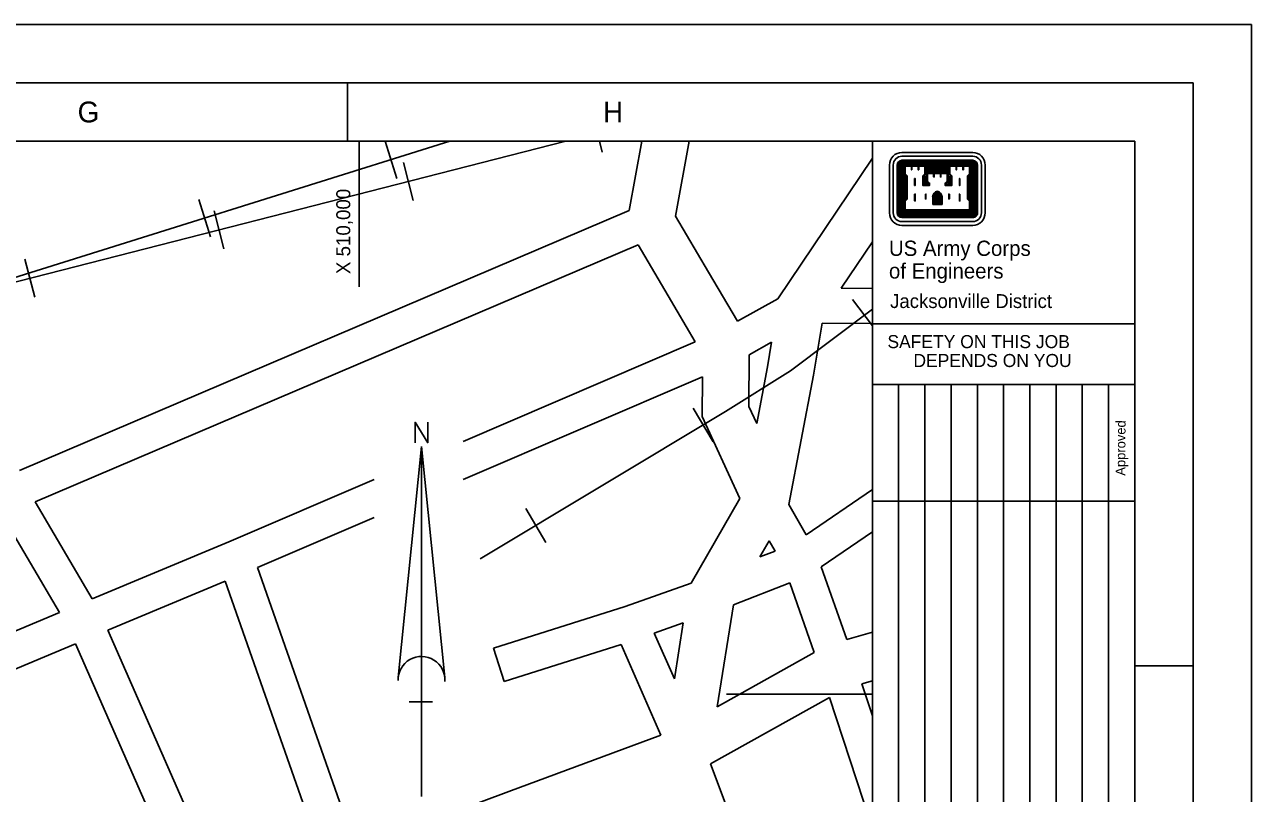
# Model space of a CAD drawing. Extents: x 503330 to 511530, y 1310349 to 1316149.
# Drawn here: x 509426 to 511530, y 1314830 to 1316149 of the extents above; entities that cross this region are included whole.
import ezdxf

# ---------------------------------------------------------------- set-up
doc = ezdxf.new("R2010")
doc.units = 0
for name, color, linetype in [('G-ANNO-SYMB', 7, 'Continuous'), ('G-ANNO-TEXT', 7, 'Continuous'), ('G-ANNO-TTLB', 7, 'Continuous'), ('Level 2', 7, 'Continuous'), ('Level 23', 7, 'Continuous'), ('Level 3', 7, 'Continuous'), ('Level 32', 7, 'Continuous'), ('Level 37', 7, 'Continuous')]:
    doc.layers.add(name, color=color, linetype=linetype)

msp = doc.modelspace()

# ---------------------------------------------------------------- linework, layer by layer
at = {"layer": 'G-ANNO-SYMB'}
for p, q in [((511052.5, 1315928.9), (510930.9, 1315928.9)), ((510930.9, 1315922.5), (511052.5, 1315922.5)), ((511052.5, 1315915.7), (510930.9, 1315915.7)), ((511052.5, 1315913.9), (510930.9, 1315913.9)), ((511052.5, 1315912.1), (510930.9, 1315912.1)), ((510909.5, 1315907.5), (510909.5, 1315825.5)), ((510915.9, 1315825.5), (510915.9, 1315907.5)), ((510922.9, 1315907.5), (510922.9, 1315825.5)), ((510924.7, 1315907.5), (510924.7, 1315825.5)), ((510926.3, 1315907.5), (510926.3, 1315825.5)), ((510928.1, 1315907.5), (510928.1, 1315825.5)), ((510929.9, 1315907.5), (510929.9, 1315825.5)), ((511052.5, 1315910.5), (510930.9, 1315910.5)), ((511052.5, 1315908.7), (510930.9, 1315908.7)), ((510931.7, 1315907.5), (510931.7, 1315826.1)), ((510933.3, 1315907.5), (510933.3, 1315827.9)), ((510973.1, 1315907.1), (511010.3, 1315907.1)), ((510973.1, 1315905.3), (511010.3, 1315905.3)), ((510973.1, 1315903.7), (511010.3, 1315903.7)), ((510973.1, 1315901.9), (511010.3, 1315901.9)), ((510973.1, 1315900.1), (511010.3, 1315900.1)), ((510973.1, 1315898.5), (511010.3, 1315898.5)), ((510973.1, 1315896.7), (511010.3, 1315896.7)), ((511050.1, 1315907.5), (511050.1, 1315827.9)), ((511051.7, 1315907.5), (511051.7, 1315826.1)), ((511053.5, 1315907.5), (511053.5, 1315825.5)), ((511055.3, 1315907.5), (511055.3, 1315825.5)), ((511056.9, 1315907.5), (511056.9, 1315825.5)), ((511058.7, 1315907.5), (511058.7, 1315825.5)), ((511060.5, 1315907.5), (511060.5, 1315825.5)), ((511067.3, 1315907.5), (511067.3, 1315825.5)), ((511073.9, 1315825.5), (511073.9, 1315907.5)), ((510934.7, 1315890.1), (510934.7, 1315848.1)), ((510936.5, 1315888.3), (510936.5, 1315850.1)), ((511046.9, 1315888.3), (511046.9, 1315850.1)), ((511048.7, 1315889.9), (511048.7, 1315848.3)), ((510983.7, 1315839.7), (510983.7, 1315853.1)), ((510985.3, 1315839.7), (510985.3, 1315853.1)), ((510987.1, 1315839.7), (510987.1, 1315853.1)), ((510988.9, 1315839.7), (510988.9, 1315853.1)), ((510990.5, 1315839.7), (510990.5, 1315853.1)), ((510992.9, 1315839.7), (510992.9, 1315853.1)), ((510994.5, 1315839.7), (510994.5, 1315853.1)), ((510996.3, 1315839.7), (510996.3, 1315853.1)), ((510998.1, 1315839.7), (510998.1, 1315853.1)), ((510999.7, 1315839.7), (510999.7, 1315853.1)), ((511050.1, 1315827.9), (510933.3, 1315827.9)), ((510983.7, 1315839.7), (510999.7, 1315839.7)), ((511052.5, 1315824.3), (510930.9, 1315824.3)), ((511052.5, 1315822.7), (510930.9, 1315822.7)), ((511052.5, 1315820.9), (510930.9, 1315820.9)), ((511052.5, 1315819.1), (510930.9, 1315819.1)), ((511052.5, 1315817.5), (510930.9, 1315817.5)), ((511052.5, 1315810.5), (510930.9, 1315810.5)), ((511051.7, 1315826.1), (510931.7, 1315826.1)), ((510930.9, 1315803.9), (511052.5, 1315803.9))]:
    msp.add_line(p, q, dxfattribs=at)
for points in [[(510934.7, 1315907.5), (510934.7, 1315891.7), (510938.1, 1315888.3), (510938.1, 1315850.1), (510934.7, 1315846.5), (510934.7, 1315829.1), (511048.7, 1315829.1), (511048.7, 1315846.5), (511045.1, 1315850.1), (511045.1, 1315888.3), (511048.7, 1315891.7), (511048.7, 1315907.5), (511033.7, 1315907.5), (511022.1, 1315907.5), (511011.3, 1315907.5), (511011.3, 1315891.7), (511015.1, 1315888.3), (511015.1, 1315874.3), (511006.7, 1315874.3), (511006.7, 1315875.7), (511010.3, 1315879.3), (511010.3, 1315894.9), (510995.3, 1315894.9), (510983.7, 1315894.9), (510973.1, 1315894.9), (510973.1, 1315879.3), (510976.7, 1315875.7), (510976.7, 1315874.3), (510968.3, 1315874.3), (510968.3, 1315888.3), (510971.9, 1315891.7), (510971.9, 1315907.5), (510956.9, 1315907.5), (510945.3, 1315907.5), (510934.7, 1315907.5)], [(510936.3, 1315905.7), (510936.3, 1315892.5), (510939.9, 1315888.9), (510939.9, 1315849.3), (510936.3, 1315845.7), (510936.3, 1315830.9), (511047.1, 1315830.9), (511047.1, 1315845.7), (511043.3, 1315849.3), (511043.3, 1315888.9), (511047.1, 1315892.5), (511047.1, 1315905.7), (511036.3, 1315905.7), (511036.3, 1315899.5), (511035.3, 1315899.5), (511035.3, 1315905.7), (511024.7, 1315905.7), (511024.7, 1315899.5), (511023.9, 1315899.5), (511023.9, 1315905.7), (511013.1, 1315905.7), (511013.1, 1315892.5), (511016.7, 1315888.9), (511016.7, 1315872.7), (511005.1, 1315872.7), (511005.1, 1315876.5), (511008.7, 1315880.1), (511008.7, 1315893.3), (510997.9, 1315893.3), (510997.9, 1315887.1), (510997.1, 1315887.1), (510997.1, 1315893.3), (510986.3, 1315893.3), (510986.3, 1315887.1), (510985.3, 1315887.1), (510985.3, 1315893.3), (510974.7, 1315893.3), (510974.7, 1315880.1), (510978.3, 1315876.5), (510978.3, 1315872.7), (510966.7, 1315872.7), (510966.7, 1315888.9), (510970.3, 1315892.5), (510970.3, 1315905.7), (510959.7, 1315905.7), (510959.7, 1315899.5), (510958.7, 1315899.5), (510958.7, 1315905.7), (510947.9, 1315905.7), (510947.9, 1315899.5), (510947.1, 1315899.5), (510947.1, 1315905.7), (510936.3, 1315905.7)], [(510952.7, 1315884.3), (510952.7, 1315872.7), (510953.9, 1315872.7), (510953.9, 1315884.3), (510952.7, 1315884.3)], [(510971.1, 1315888.5), (510970.1, 1315887.5), (510970.1, 1315876.1), (510973.9, 1315876.1), (510971.3, 1315878.7), (510971.3, 1315888.7)], [(511012.3, 1315888.5), (511013.3, 1315887.5), (511013.3, 1315876.1), (511009.7, 1315876.1), (511012.1, 1315878.7), (511012.1, 1315888.7)], [(511030.5, 1315884.3), (511030.5, 1315872.7), (511029.5, 1315872.7), (511029.5, 1315884.3), (511030.5, 1315884.3)], [(510952.7, 1315857.7), (510952.7, 1315845.9), (510953.9, 1315845.9), (510953.9, 1315857.7), (510952.7, 1315857.7)], [(510971.1, 1315857.7), (510971.1, 1315849.5), (510972.1, 1315849.5), (510972.1, 1315857.7), (510971.1, 1315857.7)], [(511012.3, 1315857.7), (511012.3, 1315849.5), (511011.3, 1315849.5), (511011.3, 1315857.7), (511012.3, 1315857.7)], [(511030.5, 1315857.7), (511030.5, 1315845.9), (511029.5, 1315845.9), (511029.5, 1315857.7), (511030.5, 1315857.7)]]:
    msp.add_lwpolyline(points, dxfattribs=at)
for centre, major_axis, start_param, end_param in [((510931, 1315907.6), (21.4, 0), 1.57078, 3.141576), ((510931, 1315907.6), (15, 0), 1.57078, 3.141576), ((510931, 1315907.6), (8.04, 0), 1.57078, 3.141576), ((510931, 1315907.6), (6.3, 0), 1.57078, 3.141576), ((510931, 1315907.6), (4.56, 0), 1.57078, 3.141576), ((511052.4, 1315907.6), (21.4, 0), 6.283169, 7.853965), ((511052.4, 1315907.6), (15, 0), 6.28317, 7.853966), ((511052.4, 1315907.6), (8.04, 0), 6.283169, 7.853965), ((511052.4, 1315907.6), (6.3, 0), 6.283169, 7.853965), ((511052.4, 1315907.6), (4.56, 0), 6.283169, 7.853965), ((510931, 1315907.6), (2.83, 0), 1.57078, 3.141576), ((510931, 1315907.6), (1.09, 0), 1.57078, 3.141576), ((511052.4, 1315907.6), (2.83, 0), 6.283169, 7.853965), ((511052.4, 1315907.6), (1.09, 0), 6.283169, 7.853965), ((510994.7, 1315852.2), (-11.1, 0), 4.985832, 6.214359), ((510994.7, 1315852.2), (-9.37, 0), 4.947465, 6.21436), ((510994.7, 1315852.2), (-7.63, 0), 4.947465, 6.21436), ((510994.7, 1315852.2), (-5.9, 0), 4.947465, 6.21436), ((510988.7, 1315852.2), (4.16, 0), 0.068794, 1.335689), ((510988.7, 1315852.2), (5.9, 0), 0.068794, 1.335689), ((510988.7, 1315852.2), (7.63, 0), 0.068795, 1.335689), ((510994.7, 1315852.2), (-4.16, 0), 4.947465, 6.214359), ((510988.7, 1315852.2), (9.37, 0), 0.068795, 1.335689), ((510988.7, 1315852.2), (11.1, 0), 0.068795, 1.29842), ((510931, 1315825.5), (-21.4, 0), 6.28317, 7.853966), ((510931, 1315825.5), (-15, 0), 6.28317, 7.853966), ((510931, 1315825.5), (-8.04, 0), 6.28317, 7.853966), ((510931, 1315825.5), (-6.3, 0), 6.28317, 7.853966), ((510931, 1315825.5), (-4.56, 0), 6.28317, 7.853966), ((510931, 1315825.5), (-2.83, 0), 6.28317, 7.853966), ((510931, 1315825.5), (-1.09, 0), 6.28317, 7.853966), ((511052.4, 1315825.5), (8.04, 0), 4.712373, 6.28317), ((511052.4, 1315825.5), (6.3, 0), 4.712373, 6.28317), ((511052.4, 1315825.5), (4.56, 0), 4.712373, 6.28317), ((511052.4, 1315825.5), (2.83, 0), 4.712373, 6.28317), ((511052.4, 1315825.5), (1.09, 0), 4.712373, 6.28317), ((511052.4, 1315825.5), (21.4, 0), 4.712373, 6.28317), ((511052.4, 1315825.5), (-15, 0), 1.570781, 3.141577)]:
    msp.add_ellipse(centre, major_axis=major_axis, ratio=0.99964, start_param=start_param, end_param=end_param, dxfattribs=at)
at = {"layer": 'G-ANNO-TTLB'}
for p, q in [((511430.3, 1316048.5), (503430.3, 1316048.5)), ((509980.3, 1315948.5), (509980.3, 1316048.5)), ((511430.3, 1310448.5), (511430.3, 1316048.5)), ((503680.3, 1315948.5), (511330.3, 1315948.5)), ((510880.3, 1310548.5), (510880.3, 1315948.5)), ((511330.3, 1315948.5), (511330.3, 1310548.5)), ((511330.3, 1315635.1), (510880.3, 1315635.1)), ((510925.3, 1313931.1), (510925.3, 1315530.9)), ((510970.3, 1313931.1), (510970.3, 1315530.9)), ((511015.3, 1313931.1), (511015.3, 1315530.9)), ((511060.3, 1313931.1), (511060.3, 1315530.9)), ((511105.3, 1313931.1), (511105.3, 1315530.9)), ((511150.3, 1313931.1), (511150.3, 1315530.9)), ((511195.3, 1313931.1), (511195.3, 1315530.9)), ((511240.3, 1313931.1), (511240.3, 1315530.9)), ((511285.3, 1313931.1), (511285.3, 1315530.9)), ((510880.3, 1315330.9), (511330.3, 1315330.9)), ((511430.3, 1315048.5), (511330.3, 1315048.5))]:
    msp.add_line(p, q, dxfattribs=at)
for points in [[(503330.3, 1310348.5), (511530.3, 1310348.5), (511530.3, 1316148.5), (503330.3, 1316148.5)], [(503330.3, 1310348.5), (511530.3, 1310348.5), (511530.3, 1316148.5), (503330.3, 1316148.5)], [(503330.3, 1316148.5), (511530.3, 1316148.5), (511530.3, 1310348.5), (503330.3, 1310348.5)]]:
    msp.add_lwpolyline(points, close=True, dxfattribs=at)
for points in [[(511480.3, 1316148.5), (511530.3, 1316148.5), (511530.3, 1316098.5)], [(511330.3, 1315530.9), (510880.3, 1315530.9)]]:
    msp.add_lwpolyline(points, dxfattribs=at)
at = {"layer": 'Level 2'}
for p, q in [((510000, 1315698.5), (510000, 1315948.5)), ((510067.3, 1315028.8), (510107.1, 1315424.8)), ((510107.1, 1314824.8), (510107.1, 1315424.8)), ((510146.9, 1315028.8), (510107.1, 1315424.8)), ((510126.1, 1314986.9), (510086.1, 1314986.9)), ((510630.3, 1315000), (510880.3, 1315000))]:
    msp.add_line(p, q, dxfattribs=at)
msp.add_lwpolyline([(510096.1, 1315431.3), (510096.1, 1315466.3), (510117.8, 1315431.3), (510117.8, 1315466.3)], dxfattribs=at)
msp.add_arc((510107.1, 1315024.8), 40, 355.2984, 182.0673, dxfattribs=at)
at = {"layer": 'Level 23'}
for p, q in [((510463.1, 1315829.3), (510484.7, 1315948.5)), ((510542.7, 1315820.1), (510566, 1315948.5)), ((510718.3, 1315678.3), (510880.3, 1315919.6)), ((510826.6, 1315696.1), (510880.3, 1315776.1)), ((510779.3, 1315547.4), (510794, 1315636.2)), ((510700.6, 1315561.4), (510707.5, 1315603.5)), ((510668.7, 1315493.6), (510669, 1315582)), ((510700.6, 1315561.4), (510682, 1315464.3)), ((510588.6, 1315476.4), (510588.9, 1315544.2)), ((510779.3, 1315547.4), (510737, 1315325.4)), ((510682, 1315464.3), (510668.7, 1315493.6)), ((510652.9, 1315335.6), (510588.6, 1315476.4)), ((510652.9, 1315335.6), (510569.3, 1315190.5)), ((510703.4, 1315263.1), (510687.5, 1315235.4)), ((510614.3, 1314978.6), (510641.9, 1315153.4)), ((510540.8, 1315026.1), (510556, 1315122.1)), ((510836.4, 1315093.9), (510880.3, 1315106.1)), ((510614.3, 1314978.6), (510780.7, 1315071.5)), ((510862.2, 1315018), (510880.3, 1315023.1)), ((510602.7, 1314880.5), (510806.8, 1314994.4)), ((510257, 1314833.1), (510517.6, 1314929.8)), ((509994.9, 1314735.8), (510257, 1314833.1))]:
    msp.add_line(p, q, dxfattribs=at)
for points in [[(510648.8, 1315639.5), (510599.4, 1315723.6), (510542.7, 1315820.1)], [(510576.7, 1315604.3), (510530.4, 1315683.1), (510478.9, 1315770.8)]]:
    msp.add_lwpolyline(points, dxfattribs=at)
at = {"layer": 'Level 32'}
for p, q in [((509418, 1315383.9), (510463.1, 1315829.3)), ((509444.4, 1315329.9), (510478.9, 1315770.8)), ((510826.6, 1315696.1), (510880.3, 1315695.9)), ((510648.8, 1315639.5), (510718.3, 1315678.3)), ((510794, 1315636.2), (510880.3, 1315635.9)), ((510178.5, 1315433.5), (510576.7, 1315604.3)), ((510669, 1315582), (510707.5, 1315603.5)), ((510178.5, 1315368.3), (510588.9, 1315544.2)), ((509776.5, 1315261.2), (510026, 1315368.2)), ((510766.7, 1315273.3), (510880.3, 1315351.3)), ((509542.2, 1315163.3), (509444.4, 1315329.9)), ((510766.7, 1315273.3), (510737, 1315325.4)), ((509486.3, 1315140), (509387.1, 1315309.1)), ((509825.9, 1315217.1), (510026, 1315302.9)), ((509542.2, 1315163.3), (509776.5, 1315261.2)), ((510713.5, 1315245.5), (510703.4, 1315263.1)), ((510792.7, 1315218.3), (510880.3, 1315278.5)), ((510687.5, 1315235.4), (510713.5, 1315245.5)), ((509994.9, 1314735.8), (509825.9, 1315217.1)), ((510836.4, 1315093.9), (510792.7, 1315218.3)), ((509569.4, 1315109.6), (509770.5, 1315193.7)), ((509938.1, 1314716.3), (509770.5, 1315193.7)), ((510456.3, 1315150.5), (510569.3, 1315190.5)), ((510641.9, 1315153.4), (510738.8, 1315190.9)), ((510780.7, 1315071.5), (510738.8, 1315190.9)), ((509285.2, 1315055.9), (509486.3, 1315140)), ((510230.5, 1315078.8), (510456.3, 1315150.5)), ((510506.3, 1315104.6), (510556, 1315122.1)), ((509766.3, 1314661.7), (509569.4, 1315109.6)), ((510540.8, 1315026.1), (510506.3, 1315104.6)), ((509306.3, 1314999.7), (509514, 1315086.5)), ((509710.2, 1314640.1), (509514, 1315086.5)), ((510230.5, 1315078.8), (510248.7, 1315021.6)), ((510248.7, 1315021.6), (510449.3, 1315085.3)), ((510517.6, 1314929.8), (510449.3, 1315085.3)), ((510880.3, 1314962.9), (510862.2, 1315018)), ((510879.4, 1314773.8), (510806.8, 1314994.4)), ((510675, 1314688.4), (510602.7, 1314880.5))]:
    msp.add_line(p, q, dxfattribs=at)
at = {"layer": 'Level 37'}
for p, q in [((510155.9, 1315948.5), (509273.4, 1315671.8)), ((510044.7, 1315948.5), (510064.7, 1315884.6)), ((510417.1, 1315929.8), (510412.3, 1315948.5)), ((510092.7, 1315846.7), (510076, 1315912)), ((509725.1, 1315848.7), (509745.2, 1315784.5)), ((509768.3, 1315763.7), (509751.6, 1315829)), ((509443.9, 1315680.7), (509427.2, 1315745.9)), ((510846.4, 1315676.9), (510880.3, 1315631.9)), ((510572.8, 1315490.7), (510607.5, 1315433)), ((510285.8, 1315318.2), (510320.5, 1315260.4))]:
    msp.add_line(p, q, dxfattribs=at)
for points in [[(509273.4, 1315671.8), (510354.6, 1315948.5)], [(510880.3, 1315660.4), (510739.9, 1315554.4), (510628.6, 1315485), (510208, 1315232.1)]]:
    msp.add_lwpolyline(points, dxfattribs=at)

# ---------------------------------------------------------------- texts
at = {"layer": 'G-ANNO-TEXT'}
for s, height, p in [('US Army Corps', 26.172, (510908.7, 1315751.7)), ('of Engineers', 26.172, (510908.7, 1315712.9)), ('Jacksonville District', 23.8, (510910.7, 1315662.3)), ('SAFETY ON THIS JOB', 22.397, (510906.1, 1315593.5)), ('DEPENDS ON YOU', 22.397, (510950.7, 1315561.1))]:
    msp.add_text(s, height=height, dxfattribs=at).set_placement(p)
msp.add_text('Approved', height=16.6, rotation=89.6609, dxfattribs=at).set_placement((511313.9, 1315374.7))
at = {"layer": 'G-ANNO-TTLB'}
for s, p in [('G', (509517.5, 1315980.7)), ('H', (510418.3, 1315980.7))]:
    msp.add_text(s, height=35.7, dxfattribs=at).set_placement(p)
at = {"layer": 'Level 3'}
msp.add_text('X 510,000', height=24, rotation=90, dxfattribs=at).set_placement((509985, 1315720.5))

doc.saveas('drawing.dxf')
